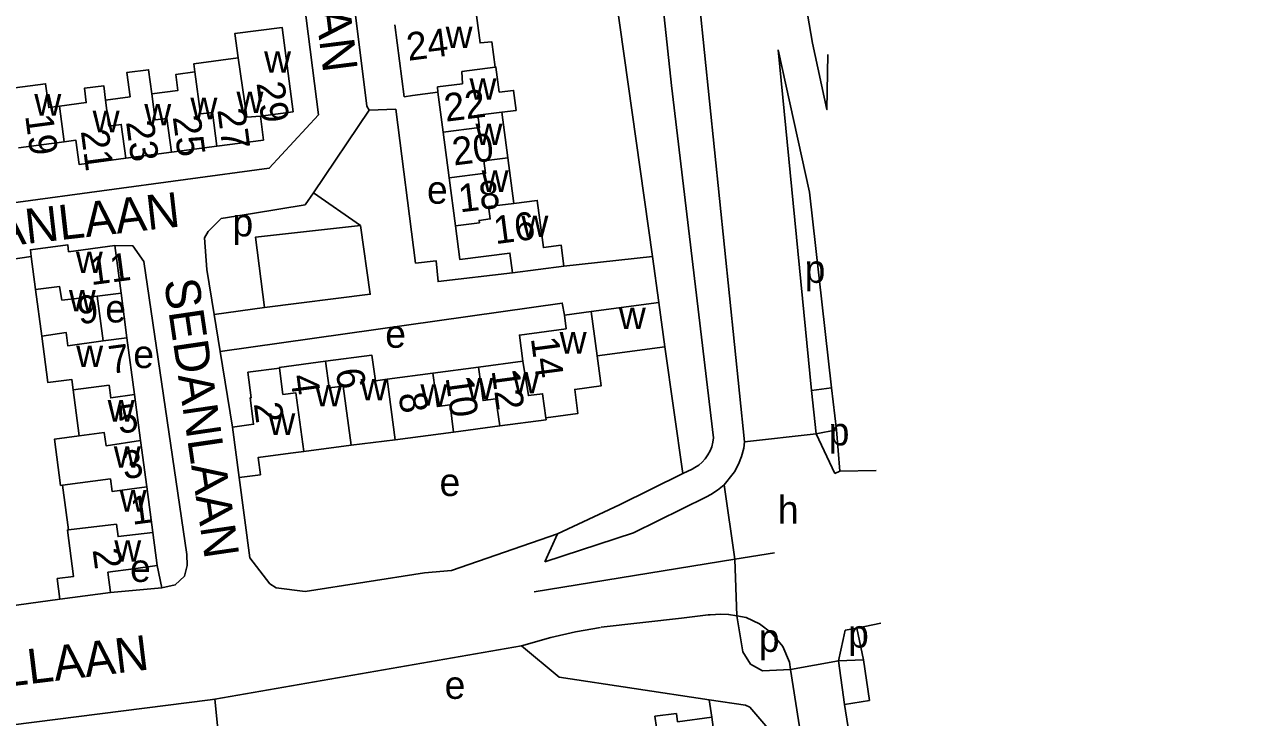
# Model space of a CAD drawing. Extents: x 157768 to 159790, y 387230 to 389604.
# Drawn here: x 159351.4 to 159528.6, y 389072.5 to 389171.9 of the extents above; entities that cross this region are included whole.
import ezdxf

# ---------------------------------------------------------------- set-up
doc = ezdxf.new("R2010")
doc.units = 0
for name, color, linetype in [('BLT_Basislijn', 7, 'Continuous'), ('BLT_Bebouwing', 7, 'Continuous'), ('BLT_Centroide', 7, 'Continuous'), ('BLT_Huisnummer', 7, 'Continuous'), ('BLT_Huisnummer_ tussenligend', 7, 'Continuous'), ('BLT_Onderverdeling_panden', 7, 'Continuous'), ('BLT_Straatnaam', 7, 'Continuous'), ('BLT_Vlakafsluiter', 7, 'Continuous')]:
    doc.layers.add(name, color=color, linetype=linetype)

msp = doc.modelspace()

# ---------------------------------------------------------------- linework, layer by layer
at = {"layer": 'BLT_Basislijn'}
for p, q in [((159441.49, 389138.62), (159432.64, 389201.14)), ((159459.55, 389168.24), (159464.29, 389119.37)), ((159444.23, 389163.15), (159450.26, 389112.62)), ((159392.85, 389147.73), (159400.86, 389159.61)), ((159339.04, 389136.74), (159352.36, 389138.59)), ((159428.77, 389137.23), (159441.49, 389138.62)), ((159442.43, 389132.01), (159441.49, 389138.62)), ((159366.06, 389126.97), (159365.24, 389133.37)), ((159378.6, 389130.29), (159379.47, 389125.01)), ((159379.47, 389125.01), (159381.25, 389114.15)), ((159443.27, 389125.67), (159445.85, 389107.48)), ((159467.19, 389119.78), (159467.88, 389113.76)), ((159464.29, 389119.37), (159465, 389113.19)), ((159467.88, 389113.76), (159465, 389113.19)), ((159465, 389113.19), (159467.67, 389107.48)), ((159445.85, 389107.48), (159436.78, 389103.01)), ((159447.17, 389108.13), (159445.85, 389107.48)), ((159453.07, 389107.47), (159451.76, 389105.88)), ((159467.67, 389107.48), (159468.39, 389107.82)), ((159436.78, 389103.01), (159427.88, 389098.84)), ((159424.51, 389090.52), (159453.33, 389095.2)), ((159453.33, 389095.2), (159459.01, 389096.12)), ((159371.1, 389091.07), (159370.45, 389094.29)), ((159371.1, 389091.07), (159363.75, 389090.41)), ((159343.16, 389087.66), (159356.48, 389089.45)), ((159468.85, 389083.69), (159469.13, 389085.01)), ((159470.83, 389085.29), (159471.77, 389080.79)), ((159378.7, 389075.14), (159422.7, 389082.77)), ((159471.77, 389080.79), (159468.2, 389080.63)), ((159468.2, 389080.63), (159469.05, 389074.35)), ((159379.63, 389065.73), (159378.7, 389075.14)), ((159449.62, 389075.03), (159450.02, 389072.53)), ((159472.65, 389074.93), (159469.05, 389074.35))]:
    msp.add_line(p, q, dxfattribs=at)
for points in [[(159466.65, 389167.57), (159466.53, 389159.68), (159464.46, 389169.2), (159463.51, 389174.73), (159461.68, 389191.02), (159459.24, 389215.81), (159456.83, 389229.26), (159455.18, 389236.07), (159451.75, 389258.67), (159450.84, 389266.98)], [(159437.93, 389251.95), (159439.58, 389227.77), (159441.98, 389184.21), (159444.23, 389163.15)], [(159442.11, 389240.74), (159443.23, 389223.74), (159454.72, 389112.02)], [(159394.58, 389207.44), (159394.75, 389206.21), (159400.49, 389160.18), (159400.86, 389159.61)], [(159323.39, 389142.32), (159326.44, 389143.16), (159386.5, 389151.27), (159393.58, 389158.95), (159389.74, 389188.96), (159389.62, 389189.85)], [(159459.55, 389168.24), (159464.01, 389147.82), (159467.19, 389119.78)], [(159400.86, 389159.61), (159404.66, 389159.72), (159407.51, 389137.67), (159410.45, 389137.99), (159410.73, 389135.02), (159421.4, 389136.26)], [(159392.85, 389147.73), (159391.65, 389146.04), (159384.09, 389144.78)], [(159399.61, 389143.08), (159392.85, 389147.73)], [(159384.09, 389144.78), (159379.62, 389144.04), (159377.73, 389142.21), (159377.24, 389141.27), (159377.54, 389136.74), (159378.6, 389130.29)], [(159385.82, 389131.3), (159384.53, 389141.36), (159399.61, 389143.08)], [(159385.82, 389131.3), (159400.99, 389133.2), (159399.61, 389143.08)], [(159364.33, 389140.18), (159366.95, 389140.14), (159368.53, 389137.87), (159374.7, 389095.86), (159374.74, 389094.29), (159374.37, 389092.79), (159373.03, 389091.51), (159371.1, 389091.07)], [(159378.6, 389130.29), (159385.82, 389131.3)], [(159428.85, 389130.21), (159428.55, 389131.93), (159379.47, 389125.01)], [(159464.29, 389119.37), (159467.19, 389119.78)], [(159450.26, 389112.62), (159450.17, 389111.97), (159450.01, 389111.33), (159449.77, 389110.72), (159449.45, 389110.15), (159449.07, 389109.61), (159448.63, 389109.13), (159448.13, 389108.7), (159447.58, 389108.34), (159447.17, 389108.13)], [(159468.39, 389107.82), (159467.88, 389113.76)], [(159454.72, 389112.02), (159454.6, 389111.1), (159454.29, 389109.93), (159453.85, 389108.81), (159453.27, 389107.75), (159453.07, 389107.47)], [(159382.21, 389106.9), (159383.7, 389095.4), (159386.6, 389091.66), (159387.52, 389091.1), (159391.65, 389090.56), (159408.77, 389093.23)], [(159451.76, 389105.88), (159450.84, 389105.1), (159449.87, 389104.46), (159449.25, 389104.14)], [(159449.25, 389104.14), (159438.77, 389098.97), (159426.05, 389094.84)], [(159408.77, 389093.23), (159412.68, 389093.59), (159427.88, 389098.84)], [(159427.88, 389098.84), (159426.05, 389094.84)], [(159453.62, 389087.07), (159452.41, 389087.29), (159451.31, 389087.33), (159449.75, 389087.24), (159449.48, 389087.22), (159445.64, 389086.72), (159434.14, 389085.43)], [(159453.62, 389087.07), (159454.46, 389081.9), (159455.56, 389080.16), (159457.26, 389079.18), (159461.32, 389079.4)], [(159461.32, 389079.4), (159461.16, 389080.41), (159460.19, 389082.66), (159458.62, 389084.6), (159456.83, 389085.92), (159454.92, 389086.84), (159453.62, 389087.07)], [(159434.02, 389085.41), (159430.46, 389084.77), (159426.89, 389083.96), (159422.7, 389082.77)], [(159469.13, 389085.01), (159470.83, 389085.29)], [(159422.7, 389082.77), (159428.1, 389078.3), (159449.62, 389075.03)], [(159468.2, 389080.63), (159468.85, 389083.69)], [(159471.77, 389080.79), (159472.65, 389074.93)], [(159461.32, 389079.4), (159477.78, 388974.22), (159484.29, 388935.47), (159487.52, 388916.28), (159495.82, 388873.83)], [(159321.07, 389067.79), (159378.02, 389075.05), (159378.7, 389075.14)], [(159449.62, 389075.03), (159454.85, 389074.28), (159455.48, 389073.96), (159458.03, 389070.98), (159483.81, 388911.81), (159494.05, 388855.63), (159516.92, 388737.84), (159528.56, 388690.88), (159519.15, 388688.67)], [(159469.05, 389074.35), (159473.88, 389043.99)]]:
    msp.add_lwpolyline(points, dxfattribs=at)
at = {"layer": 'BLT_Bebouwing'}
for p, q in [((159419.88, 389159.31), (159420.74, 389152.78)), ((159412.32, 389149.9), (159411.46, 389156.44)), ((159350.51, 389154.19), (159357.06, 389155.05)), ((159365.92, 389152.7), (159372.46, 389153.56)), ((159372.46, 389153.56), (159378.99, 389154.43)), ((159428.77, 389137.23), (159421.4, 389136.26)), ((159428.85, 389130.21), (159432.7, 389130.72)), ((159432.7, 389130.72), (159442.43, 389132.01)), ((159429.11, 389128.23), (159428.85, 389130.21)), ((159362.67, 389126.52), (159366.06, 389126.97)), ((159403.43, 389121.02), (159410, 389121.9)), ((159410, 389121.9), (159416.55, 389122.76)), ((159358.37, 389119.47), (159359.24, 389112.88)), ((159382.21, 389106.9), (159381.25, 389114.15)), ((159419.58, 389114.32), (159412.93, 389113.44)), ((159368.04, 389112.2), (159368.93, 389105.6)), ((159404.58, 389112.34), (159398.25, 389111.54)), ((159357.7, 389099.39), (159356.85, 389105.82)), ((159368.93, 389105.6), (159369.82, 389099.01)), ((159363.75, 389090.41), (159356.48, 389089.45))]:
    msp.add_line(p, q, dxfattribs=at)
for points in [[(159412.86, 389174.94), (159412.91, 389174.54), (159416.01, 389174.94), (159416.77, 389169.23), (159418.45, 389169.39), (159418.93, 389165.76)], [(159382.03, 389167.1), (159381.57, 389170.57), (159388.35, 389171.46), (159389.94, 389159.38), (159385.23, 389158.76)], [(159410.7, 389162.16), (159407.04, 389161.68), (159405.87, 389161.53), (159404.51, 389171.85)], [(159375.85, 389165.1), (159375.7, 389166.26), (159379.54, 389166.77), (159382.03, 389167.1)], [(159418.93, 389165.76), (159419.03, 389165.77), (159419.5, 389162.18), (159421.56, 389162.44), (159421.93, 389159.57), (159419.88, 389159.31)], [(159363.03, 389161.05), (159366.53, 389161.51), (159366.07, 389164.99), (159369.19, 389165.4), (159369.65, 389161.93)], [(159369.65, 389161.93), (159373.41, 389162.42), (159373.11, 389164.73), (159375.85, 389165.1)], [(159347.76, 389162.5), (159354.41, 389163.38), (159354.86, 389159.97), (159356.39, 389160.17)], [(159356.39, 389160.17), (159360.26, 389160.68), (159359.99, 389162.73), (159362.76, 389163.09), (159363.03, 389161.05)], [(159411.46, 389156.44), (159410.7, 389162.16)], [(159385.23, 389158.76), (159385.68, 389155.31), (159378.99, 389154.43)], [(159357.06, 389155.05), (159358.77, 389155.28), (159359.23, 389151.82), (159365.92, 389152.7)], [(159420.74, 389152.78), (159421.6, 389146.2)], [(159413.22, 389142.99), (159412.32, 389149.9)], [(159421.6, 389146.2), (159424.96, 389146.65), (159425.19, 389144.86), (159425.23, 389144.56)], [(159425.23, 389144.56), (159425.85, 389139.9), (159428.38, 389140.24), (159428.77, 389137.23)], [(159421.4, 389136.26), (159421.03, 389139.11), (159413.86, 389138.17), (159413.22, 389142.99)], [(159352.36, 389138.59), (159352.23, 389139.58), (159357.59, 389140.29), (159357.72, 389139.3), (159364.33, 389140.18)], [(159364.33, 389140.18), (159365.24, 389133.37)], [(159352.36, 389138.59), (159352.99, 389133.86)], [(159352.99, 389133.86), (159353.87, 389127.19)], [(159365.24, 389133.37), (159361.82, 389132.92)], [(159361.82, 389132.92), (159362.67, 389126.52)], [(159442.43, 389132.01), (159443.27, 389125.67)], [(159353.87, 389127.19), (159354.76, 389120.53), (159358.17, 389120.98), (159358.37, 389119.47)], [(159366.06, 389126.97), (159367.16, 389118.8)], [(159422.9, 389123.6), (159422.4, 389127.35), (159429.11, 389128.23)], [(159443.27, 389125.67), (159433.55, 389124.38)], [(159387.96, 389122.6), (159387.95, 389122.7), (159394.6, 389123.58)], [(159394.6, 389123.58), (159401.24, 389124.46), (159401.73, 389120.8), (159403.43, 389121.02)], [(159416.55, 389122.76), (159422.9, 389123.6)], [(159433.55, 389124.38), (159434.13, 389120.05), (159430.34, 389119.54), (159430.79, 389116.1), (159426.19, 389115.46)], [(159381.25, 389114.15), (159384.27, 389114.55), (159383.77, 389118.33), (159383.92, 389118.35), (159383.44, 389122), (159387.96, 389122.6)], [(159367.16, 389118.8), (159368.04, 389112.2)], [(159426.19, 389115.46), (159426.23, 389115.2), (159419.58, 389114.32)], [(159359.24, 389112.88), (159355.69, 389112.41), (159356.56, 389105.79), (159356.85, 389105.82)], [(159412.93, 389113.44), (159404.58, 389112.34)], [(159398.25, 389111.54), (159391.45, 389110.64)], [(159389.58, 389110.39), (159384.91, 389109.77), (159385.24, 389107.3), (159382.21, 389106.9)], [(159391.45, 389110.64), (159389.58, 389110.39)], [(159356.48, 389089.45), (159356.09, 389092.43), (159358.44, 389092.74), (159357.56, 389099.37), (159357.7, 389099.39)], [(159369.82, 389099.01), (159370.45, 389094.29)], [(159370.45, 389094.29), (159367.05, 389093.83), (159363.36, 389093.34), (159363.75, 389090.41)], [(159436.51, 389070.32), (159442.06, 389071.05), (159441.85, 389072.68), (159444.94, 389073.08)], [(159450.02, 389072.53), (159445.1, 389071.88), (159444.94, 389073.08)], [(159451.61, 389060.69), (159450.77, 389066.86), (159450.02, 389072.53)]]:
    msp.add_lwpolyline(points, dxfattribs=at)
at = {"layer": 'BLT_Onderverdeling_panden'}
for p, q in [((159357.06, 389155.05), (159356.39, 389160.17)), ((159432.7, 389130.72), (159433.55, 389124.38)), ((159403.43, 389121.02), (159404.58, 389112.34))]:
    msp.add_line(p, q, dxfattribs=at)
for points in [[(159385.23, 389158.76), (159383.27, 389158.6), (159382.03, 389167.1)], [(159410.7, 389162.16), (159410.67, 389162.92), (159414.23, 389163.38), (159414.15, 389165.13), (159418.93, 389165.76)], [(159378.99, 389154.43), (159378.35, 389159.28), (159376.66, 389159.06), (159375.85, 389165.1)], [(159365.92, 389152.7), (159365.27, 389157.55), (159363.51, 389157.32), (159363.03, 389161.05)], [(159372.46, 389153.56), (159371.81, 389158.42), (159370.15, 389158.2), (159369.65, 389161.93)], [(159411.46, 389156.44), (159416.67, 389157.1), (159416.44, 389158.88), (159419.88, 389159.31)], [(159412.32, 389149.9), (159417.54, 389150.56), (159417.31, 389152.34), (159420.74, 389152.78)], [(159413.22, 389142.99), (159416.66, 389143.44), (159416.61, 389143.79), (159418.21, 389143.99), (159417.99, 389145.78), (159421.6, 389146.2)], [(159361.82, 389132.92), (159356.75, 389132.35), (159356.39, 389134.31), (159352.99, 389133.86)], [(159353.87, 389127.19), (159357.35, 389127.72), (159357.6, 389125.8), (159362.67, 389126.52)], [(159394.6, 389123.58), (159395.1, 389119.77), (159397.13, 389120.03), (159398.25, 389111.54)], [(159426.19, 389115.46), (159425.73, 389118.93), (159423.7, 389118.67), (159422.9, 389123.6)], [(159388.46, 389118.8), (159387.96, 389122.6)], [(159412.93, 389113.44), (159412.47, 389117.33), (159410.64, 389117.09), (159410, 389121.9)], [(159419.58, 389114.32), (159419.01, 389118.2), (159417.18, 389117.95), (159416.55, 389122.76)], [(159358.37, 389119.47), (159363.52, 389120.15), (159363.76, 389118.34), (159367.16, 389118.8)], [(159388.46, 389118.8), (159390.33, 389119.05), (159391.45, 389110.64)], [(159359.24, 389112.88), (159362.84, 389113.35), (159363.09, 389111.46), (159368.04, 389112.2)], [(159356.85, 389105.82), (159363.72, 389106.72), (159363.96, 389104.93), (159368.93, 389105.6)], [(159357.7, 389099.39), (159364.59, 389100.21), (159364.82, 389098.44), (159369.82, 389099.01)]]:
    msp.add_lwpolyline(points, dxfattribs=at)
at = {"layer": 'BLT_Vlakafsluiter'}
for p, q in [((159454.72, 389112.02), (159465, 389113.19)), ((159473.58, 389107.9), (159468.39, 389107.82)), ((159451.76, 389105.88), (159453.33, 389095.2)), ((159453.33, 389095.2), (159453.62, 389087.07)), ((159470.83, 389085.29), (159474.26, 389086.05)), ((159461.32, 389079.4), (159468.2, 389080.63))]:
    msp.add_line(p, q, dxfattribs=at)

# ---------------------------------------------------------------- texts
at = {"layer": 'BLT_Centroide'}
for s, p in [('w', (159411.81, 389168.5)), ('w', (159385.77, 389164.97)), ('w', (159415.24, 389161.09)), ('w', (159381.81, 389159.17)), ('w', (159352.8, 389158.83)), ('w', (159368.58, 389157.42)), ('w', (159375.2, 389158.3)), ('w', (159361.17, 389156.44)), ('w', (159416.1, 389154.59)), ('w', (159416.98, 389147.88)), ('e', (159409.14, 389146.18)), ('p', (159381.23, 389141.49)), ('w', (159422.69, 389141.39)), ('w', (159358.76, 389136.25)), ('p', (159463.33, 389134.83)), ('w', (159357.76, 389130.75)), ('e', (159362.99, 389129.15)), ('w', (159436.67, 389128.19)), ('e', (159403.15, 389125.52)), ('w', (159428.18, 389124.69)), ('w', (159358.81, 389122.77)), ('e', (159367, 389122.61)), ('w', (159421.39, 389118.98)), ('w', (159393.09, 389117.11)), ('w', (159399.59, 389117.98)), ('w', (159408.19, 389117.23)), ('w', (159414.8, 389118.11)), ('w', (159363.32, 389114.94)), ('w', (159386.37, 389113.03)), ('p', (159466.78, 389111.52)), ('w', (159364.2, 389108.31)), ('e', (159410.94, 389104.26)), ('w', (159365.04, 389102.03)), ('h', (159459.49, 389100.31)), ('w', (159364.27, 389094.84)), ('e', (159366.54, 389091.94)), ('p', (159456.75, 389081.91)), ('p', (159469.56, 389082.52)), ('e', (159411.67, 389075.17))]:
    msp.add_text(s, height=4, dxfattribs=at).set_placement(p)
at = {"layer": 'BLT_Huisnummer'}
for s, rotation, p in [('24', 7.3167, (159406.46, 389166.67)), ('29', 277.5305, (159384.67, 389163.49)), ('25', 277.5305, (159372.65, 389158.63)), ('21', 277.5305, (159359.46, 389156.6)), ('20', 7.2601, (159413, 389151.65)), ('16', 7.4892, (159418.96, 389140.37)), ('11', 7.5526, (159360.94, 389134.49)), ('14', 277.5398, (159424.03, 389126.89)), ('6', 277.5398, (159396.05, 389122.37)), ('10', 277.5398, (159411.8, 389121.25)), ('5', 7.5526, (159364.96, 389113.18)), ('2', 277.5398, (159384.28, 389117.5)), ('1', 7.5526, (159366.86, 389100.12)), ('2', 277.5605, (159361.15, 389096.55))]:
    msp.add_text(s, height=4, rotation=rotation, dxfattribs=at).set_placement(p)
at = {"layer": 'BLT_Huisnummer_ tussenligend'}
for s, rotation, p in [('22', 7.1818, (159411.84, 389157.93)), ('19', 277.5305, (159351.48, 389158.81)), ('27', 277.5305, (159379.05, 389159.65)), ('23', 277.5305, (159365.95, 389157.91)), ('18', 6.777, (159413.87, 389144.93)), ('9', 7.5526, (159359.23, 389128.87)), ('7', 7.5526, (159363.71, 389121.76)), ('4', 277.5398, (159389.51, 389121.5)), ('12', 277.5398, (159418.4, 389122.27)), ('8', 277.5398, (159405.06, 389118.9)), ('3', 7.5526, (159365.67, 389106.66))]:
    msp.add_text(s, height=4, rotation=rotation, dxfattribs=at).set_placement(p)
at = {"layer": 'BLT_Straatnaam'}
for s, height, rotation, p in [('SEDANLAAN', 5, 277.1755, (159389.22, 389204.99)), ('SEDANLAAN', 5, 6.4562, (159333.64, 389138.37)), ('SEDANLAAN', 5, 278.3559, (159371.4, 389135.14)), ('RIJSSELLAAN', 4.9999, 6.9585, (159325.17, 389074))]:
    msp.add_text(s, height=height, rotation=rotation, dxfattribs=at).set_placement(p)

doc.saveas('drawing.dxf')
